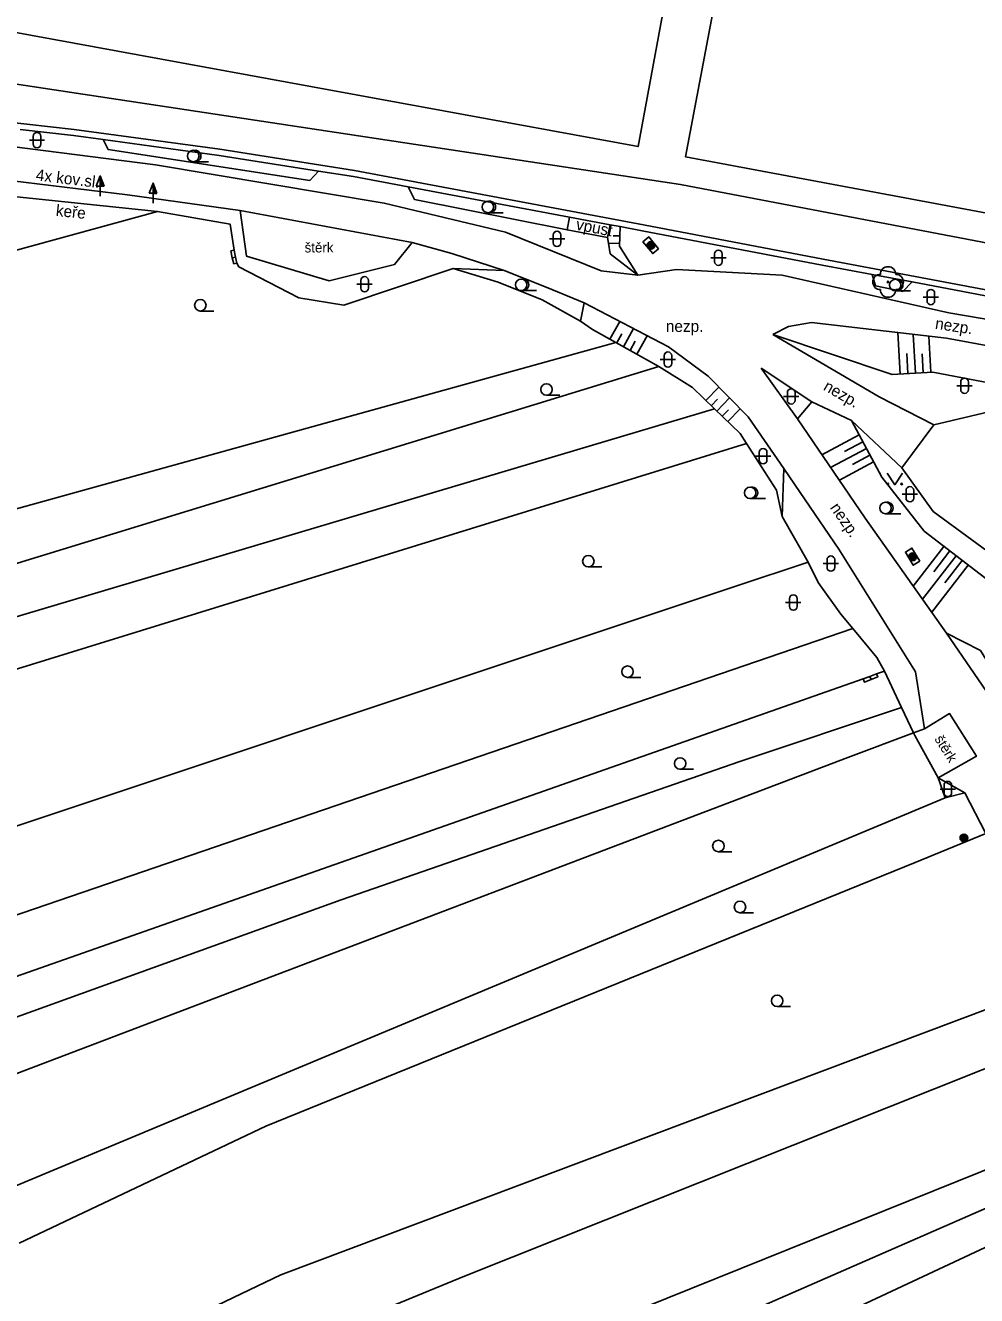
# Model space of a CAD drawing. Extents: x -595546 to -593986, y -1160845 to -1159202.
# Drawn here: x -595049.5 to -594987.4, y -1160163.2 to -1160080.3 of the extents above; entities that cross this region are included whole.
import ezdxf

# ---------------------------------------------------------------- set-up
doc = ezdxf.new("R2010")
doc.units = 0
for name, color, linetype in [('DOP - kresba z DSPS bez souradnic', 7, 'Continuous'), ('DOP - rozhrani ploch obecne', 7, 'Continuous'), ('kanalizace - povrch.  znaky - skut. velikost', 7, 'Continuous'), ('Level 22', 7, 'Continuous'), ('Level 24', 7, 'Continuous'), ('Level 25', 7, 'Continuous'), ('Level 36', 7, 'Continuous'), ('silnoproud - povrch.  znaky a  RIS  skut. velikost', 7, 'Continuous'), ('TM - dolni hrana svahu', 7, 'Continuous'), ('TM - horni hrana svahu', 7, 'Continuous'), ('TM - hranice souvisleho porostu (skupiny stromu_ kere)', 7, 'Continuous'), ('TM - letecke snimky - pomocna linie', 7, 'Continuous'), ('TM - nezpevnene cesty a chodniky', 7, 'Continuous'), ('TM - plot drateny_ kovovy - VP', 7, 'Continuous'), ('TM - podezdivka plotu - VP', 7, 'Continuous'), ('TM - popis povrchu', 7, 'Continuous'), ('TM - popis zelene', 7, 'Continuous'), ('TM - poznamka', 7, 'Continuous'), ('TM - rozhrani kultur', 7, 'Continuous'), ('TM - rozhrani ploch obecne - VP', 7, 'Continuous'), ('TM - srafovani', 7, 'Continuous'), ('TM - vjezd na pozemek', 7, 'Continuous')]:
    doc.layers.add(name, color=color, linetype=linetype)

msp = doc.modelspace()

# ---------------------------------------------------------------- linework, layer by layer
at = {"layer": 'DOP - kresba z DSPS bez souradnic'}
for points in [[(-594996.5, -1160017.71), (-595009.51, -1160088.18), (-595057.76, -1160079.35), (-595051.78, -1160044.49), (-595044.93, -1160008.53)], [(-594994.78, -1160027.28), (-595006.42, -1160088.85), (-594939.11, -1160101.43), (-594934.74, -1160078.54), (-594931.92, -1160079.05), (-594936.73, -1160104.02), (-595006.75, -1160090.67)], [(-595006.75, -1160090.67), (-595060.78, -1160082.5), (-595082.25, -1160081.41), (-595101.08, -1160081.24), (-595119.19, -1160081.99), (-595142.76, -1160083.52), (-595149.6, -1160084.27), (-595210.49, -1160092.35), (-595222.93, -1160095.19), (-595225.49, -1160095.93), (-595227.88, -1160096.99), (-595241.96, -1160105.99), (-595288.12, -1160138.81), (-595307.05, -1160111.71), (-595308.9, -1160104.34)]]:
    msp.add_lwpolyline(points, dxfattribs=at)
at = {"layer": 'DOP - rozhrani ploch obecne'}
for points in [[(-595010.97, -1160100.98), (-595064.79, -1160115.92)], [(-595053.6, -1160116.49), (-595008.16, -1160102.55)], [(-595004.53, -1160105.31), (-595063.59, -1160122.9)], [(-595002.43, -1160107.58), (-595063.52, -1160126.46)], [(-595062.49, -1160136.68), (-595003.14, -1160116.9)], [(-594995.49, -1160119.66), (-595072.53, -1160146.06)], [(-594993.94, -1160122.62), (-594993.42, -1160122.45)], [(-595060.62, -1160146.07), (-594994.81, -1160122.96)], [(-595002.86, -1160128.36), (-594992.31, -1160124.82)], [(-595052.1, -1160149.49), (-594995.81, -1160128.08)], [(-595028.9, -1160137.38), (-595002.86, -1160128.36)], [(-594994.09, -1160132.65), (-595054.14, -1160157.72)], [(-594991.43, -1160134.95), (-595033.83, -1160152.16)], [(-595060.58, -1160148.82), (-595028.9, -1160137.38)], [(-594981.93, -1160142.72), (-595032.85, -1160161.88)], [(-595020.85, -1160161.97), (-594980.93, -1160146.04)], [(-595033.83, -1160152.16), (-595049.93, -1160159.81)], [(-594979.3, -1160152), (-595029.56, -1160172.25)], [(-595027.18, -1160175.19), (-594980.21, -1160154.65)], [(-595025.32, -1160178.09), (-594977.96, -1160155.93)], [(-595032.85, -1160161.88), (-595043.2, -1160166.84)], [(-595033.86, -1160167.32), (-595020.85, -1160161.97)]]:
    msp.add_lwpolyline(points, dxfattribs=at)
at = {"layer": 'kanalizace - povrch.  znaky - skut. velikost'}
for points in [[(-595013.99, -1160092.8), (-595014.14, -1160093.62)], [(-595014.14, -1160093.62), (-595011.5, -1160094.12)], [(-595011.5, -1160094.12), (-595011.34, -1160093.29)]]:
    msp.add_lwpolyline(points, dxfattribs=at)
at = {"layer": 'Level 22'}
msp.add_circle((-594993.19, -1160097.03), 0.05, dxfattribs=at)
for centre, start, end in [((-594993.19, -1160096.53), 0, 180), ((-594993.69, -1160097.03), 90, 270), ((-594992.69, -1160097.03), 270, 90), ((-594993.19, -1160097.53), 180, 0)]:
    msp.add_arc(centre, 0.5, start, end, dxfattribs=at)
at = {"layer": 'Level 24'}
for points in [[(-595008.177, -1160094.853), (-595008.82, -1160094.088), (-595009.203, -1160094.41), (-595008.559, -1160095.175)], [(-594991.117, -1160115.27), (-594991.632, -1160114.413), (-594992.06, -1160114.67), (-594991.545, -1160115.527)]]:
    msp.add_lwpolyline(points, close=True, dxfattribs=at)
at = {"layer": 'Level 25'}
for p, q in [((-595044.892, -1160090.778), (-595044.64, -1160090.104)), ((-595044.64, -1160090.778), (-595044.892, -1160090.778)), ((-595044.64, -1160091.43), (-595044.64, -1160090.78)), ((-595041.442, -1160091.238), (-595041.19, -1160090.564)), ((-595041.19, -1160091.238), (-595041.442, -1160091.238)), ((-595041.19, -1160091.89), (-595041.19, -1160091.24))]:
    msp.add_line(p, q, dxfattribs=at)
for points in [[(-595044.39, -1160090.78), (-595044.64, -1160090.78), (-595044.64, -1160090.104), (-595044.64, -1160090.104)], [(-595044.447, -1160090.74), (-595044.6, -1160090.74), (-595044.6, -1160090.327)], [(-595044.505, -1160090.7), (-595044.56, -1160090.7), (-595044.56, -1160090.551)], [(-595040.94, -1160091.24), (-595041.19, -1160091.24), (-595041.19, -1160090.564), (-595041.19, -1160090.564)], [(-595040.997, -1160091.2), (-595041.15, -1160091.2), (-595041.15, -1160090.787)], [(-595041.055, -1160091.16), (-595041.11, -1160091.16), (-595041.11, -1160091.011)]]:
    msp.add_lwpolyline(points, close=True, dxfattribs=at)
for centre, radius in [((-595008.68, -1160094.64), 0.25), ((-595008.68, -1160094.64), 0.2), ((-595008.68, -1160094.64), 0.15), ((-595008.68, -1160094.64), 0.1), ((-595008.68, -1160094.64), 0.05), ((-594991.58, -1160114.98), 0.25), ((-594991.58, -1160114.98), 0.2), ((-594991.58, -1160114.98), 0.15), ((-594991.58, -1160114.98), 0.1), ((-594991.58, -1160114.98), 0.05), ((-594988.24, -1160133.34), 0.25), ((-594988.24, -1160133.34), 0.2), ((-594988.24, -1160133.34), 0.15), ((-594988.24, -1160133.34), 0.1), ((-594988.24, -1160133.34), 0.05)]:
    msp.add_circle(centre, radius, dxfattribs=at)
at = {"layer": 'Level 36'}
for p, q in [((-595049.266, -1160087.766), (-595048.266, -1160087.766)), ((-595049.016, -1160087.516), (-595049.016, -1160088.016)), ((-595048.516, -1160087.516), (-595048.516, -1160088.016)), ((-595038.56, -1160089.175), (-595037.56, -1160089.175)), ((-595019.32, -1160092.505), (-595018.32, -1160092.505)), ((-595015.306, -1160094.216), (-595014.306, -1160094.216)), ((-595015.056, -1160093.966), (-595015.056, -1160094.466)), ((-595014.556, -1160093.966), (-595014.556, -1160094.466)), ((-595004.766, -1160095.446), (-595003.766, -1160095.446)), ((-595004.516, -1160095.196), (-595004.516, -1160095.696)), ((-595004.016, -1160095.196), (-595004.016, -1160095.696)), ((-595027.626, -1160096.926), (-595027.626, -1160097.426)), ((-595027.126, -1160096.926), (-595027.126, -1160097.426)), ((-595027.876, -1160097.176), (-595026.876, -1160097.176)), ((-595017.15, -1160097.585), (-595016.15, -1160097.585)), ((-594992.72, -1160097.605), (-594991.72, -1160097.605)), ((-594990.646, -1160097.766), (-594990.646, -1160098.266)), ((-594990.146, -1160097.766), (-594990.146, -1160098.266)), ((-594990.896, -1160098.016), (-594989.896, -1160098.016)), ((-595038.1, -1160098.925), (-595037.225, -1160098.925)), ((-595007.816, -1160101.846), (-595007.816, -1160102.346)), ((-595007.316, -1160101.846), (-595007.316, -1160102.346)), ((-595008.066, -1160102.096), (-595007.066, -1160102.096)), ((-594988.446, -1160103.556), (-594988.446, -1160104.056)), ((-594987.946, -1160103.556), (-594987.946, -1160104.056)), ((-595015.49, -1160104.425), (-595014.615, -1160104.425)), ((-595000.016, -1160104.506), (-594999.016, -1160104.506)), ((-594999.766, -1160104.256), (-594999.766, -1160104.756)), ((-594999.266, -1160104.256), (-594999.266, -1160104.756)), ((-594988.696, -1160103.806), (-594987.696, -1160103.806)), ((-595001.846, -1160108.406), (-595000.846, -1160108.406)), ((-595001.596, -1160108.156), (-595001.596, -1160108.656)), ((-595001.096, -1160108.156), (-595001.096, -1160108.656)), ((-595002.2, -1160111.175), (-595001.2, -1160111.175)), ((-594992.266, -1160110.896), (-594991.266, -1160110.896)), ((-594992.016, -1160110.646), (-594992.016, -1160111.146)), ((-594991.516, -1160110.646), (-594991.516, -1160111.146)), ((-594993.36, -1160112.165), (-594992.36, -1160112.165)), ((-594997.176, -1160115.176), (-594997.176, -1160115.676)), ((-594996.676, -1160115.176), (-594996.676, -1160115.676)), ((-595012.76, -1160115.645), (-595011.885, -1160115.645)), ((-594997.426, -1160115.426), (-594996.426, -1160115.426)), ((-594999.626, -1160117.716), (-594999.626, -1160118.216)), ((-594999.126, -1160117.716), (-594999.126, -1160118.216)), ((-594999.876, -1160117.966), (-594998.876, -1160117.966)), ((-595010.2, -1160122.855), (-595009.325, -1160122.855)), ((-595006.77, -1160128.855), (-595005.895, -1160128.855)), ((-594989.786, -1160130.146), (-594988.786, -1160130.146)), ((-594989.536, -1160129.896), (-594989.536, -1160130.396)), ((-594989.036, -1160129.896), (-594989.036, -1160130.396)), ((-595004.27, -1160134.245), (-595003.395, -1160134.245)), ((-595002.86, -1160138.225), (-595001.985, -1160138.225)), ((-595000.43, -1160144.355), (-594999.555, -1160144.355))]:
    msp.add_line(p, q, dxfattribs=at)
msp.add_lwpolyline([(-594993.25, -1160109.52), (-594992.75, -1160110.27), (-594992.25, -1160109.52)], dxfattribs=at)
for centre, radius in [((-595038.56, -1160088.8), 0.375), ((-595019.32, -1160092.13), 0.375), ((-595017.15, -1160097.21), 0.375), ((-594992.72, -1160097.23), 0.375), ((-595038.1, -1160098.55), 0.375), ((-595015.49, -1160104.05), 0.375), ((-594993.2, -1160110.22), 0.05), ((-594992.301, -1160110.22), 0.05), ((-595002.2, -1160110.8), 0.375), ((-594993.36, -1160111.79), 0.375), ((-595012.76, -1160115.27), 0.375), ((-595010.2, -1160122.48), 0.375), ((-595006.77, -1160128.48), 0.375), ((-595004.27, -1160133.87), 0.375), ((-595002.86, -1160137.85), 0.375), ((-595000.43, -1160143.98), 0.375)]:
    msp.add_circle(centre, radius, dxfattribs=at)
for centre, radius, start, end in [((-595048.766, -1160087.516), 0.25, 0, 180), ((-595048.766, -1160088.016), 0.25, 180, 0), ((-595038.435, -1160088.8), 0.375, 260.40593, 99.59407), ((-595019.195, -1160092.13), 0.375, 260.40593, 99.59407), ((-595014.806, -1160093.966), 0.25, 0, 180), ((-595014.806, -1160094.466), 0.25, 180, 0), ((-595004.266, -1160095.196), 0.25, 0, 180), ((-595004.266, -1160095.696), 0.25, 180, 0), ((-595027.376, -1160096.926), 0.25, 0, 180), ((-595017.025, -1160097.21), 0.375, 260.40593, 99.59407), ((-594992.595, -1160097.23), 0.375, 260.40593, 99.59407), ((-595027.376, -1160097.426), 0.25, 180, 0), ((-594990.396, -1160097.766), 0.25, 0, 180), ((-594990.396, -1160098.266), 0.25, 180, 0), ((-595007.566, -1160101.846), 0.25, 0, 180), ((-595007.566, -1160102.346), 0.25, 180, 0), ((-594988.196, -1160103.556), 0.25, 0, 180), ((-594999.516, -1160104.256), 0.25, 0, 180), ((-594988.196, -1160104.056), 0.25, 180, 0), ((-594999.516, -1160104.756), 0.25, 180, 0), ((-595001.346, -1160108.156), 0.25, 0, 180), ((-595001.346, -1160108.656), 0.25, 180, 0), ((-595002.075, -1160110.8), 0.375, 260.40593, 99.59407), ((-594991.766, -1160110.646), 0.25, 0, 180), ((-594991.766, -1160111.146), 0.25, 180, 0), ((-594993.235, -1160111.79), 0.375, 260.40593, 99.59407), ((-594996.926, -1160115.176), 0.25, 0, 180), ((-594996.926, -1160115.676), 0.25, 180, 0), ((-594999.376, -1160117.716), 0.25, 0, 180), ((-594999.376, -1160118.216), 0.25, 180, 0), ((-594989.286, -1160129.896), 0.25, 0, 180), ((-594989.286, -1160130.396), 0.25, 180, 0)]:
    msp.add_arc(centre, radius, start, end, dxfattribs=at)
at = {"layer": 'silnoproud - povrch.  znaky a  RIS  skut. velikost'}
for points in [[(-595036.11, -1160095), (-595035.9, -1160094.95)], [(-595036.02, -1160095.46), (-595036.11, -1160095)], [(-595035.8, -1160095.41), (-595036.02, -1160095.46)], [(-595035.9, -1160094.95), (-595035.85, -1160095.18)], [(-595035.85, -1160095.18), (-595035.8, -1160095.41)], [(-595035.75, -1160095.6), (-595035.8, -1160095.41)], [(-595036.02, -1160095.46), (-595035.92, -1160095.84)], [(-595035.92, -1160095.84), (-595035.71, -1160095.8)], [(-595035.71, -1160095.8), (-595035.75, -1160095.6)], [(-594994.37, -1160122.79), (-594994.81, -1160122.96)], [(-594993.94, -1160122.62), (-594994.37, -1160122.79)], [(-594994.29, -1160123), (-594994.37, -1160122.79)], [(-594993.94, -1160122.62), (-594993.86, -1160122.83), (-594994.29, -1160123)], [(-594994.29, -1160123), (-594994.73, -1160123.17), (-594994.81, -1160122.96)]]:
    msp.add_lwpolyline(points, dxfattribs=at)
at = {"layer": 'TM - dolni hrana svahu'}
msp.add_lwpolyline([(-595009.54, -1160096.58), (-595011.34, -1160095.19), (-595011.44, -1160094.49), (-595011.5, -1160094.12)], dxfattribs=at)
at = {"layer": 'TM - horni hrana svahu'}
for points in [[(-595009.54, -1160096.58), (-595010.73, -1160094.69), (-595010.69, -1160093.41)], [(-594990.26, -1160102.92), (-594992.92, -1160103.07), (-595000.71, -1160100.47)], [(-594983.3, -1160104.25), (-594990.26, -1160102.92)], [(-595000.11, -1160112.34), (-594999.99, -1160109.22)]]:
    msp.add_lwpolyline(points, dxfattribs=at)
at = {"layer": 'TM - hranice souvisleho porostu (skupiny stromu_ kere)'}
for points in [[(-595030.39, -1160089.78), (-595030.96, -1160090.4), (-595044.12, -1160088.37), (-595044.45, -1160087.72)], [(-595014.14, -1160093.62), (-595024.11, -1160091.65), (-595024.52, -1160090.81)], [(-595021.6, -1160096.14), (-595018.26, -1160096.27)], [(-594991.62, -1160097.03), (-594992.22, -1160097.64), (-594994.01, -1160097.29), (-594994.23, -1160096.54)], [(-595013.28, -1160099.58), (-595013.04, -1160098.38)], [(-594998.17, -1160104.86), (-594999.11, -1160105.97)], [(-594995.58, -1160106.08), (-594993.59, -1160109.78)], [(-594993.59, -1160109.78), (-594990.84, -1160113.3)], [(-594990.84, -1160113.3), (-594985.96, -1160117.05)], [(-594989.37, -1160119.96), (-594987.16, -1160121.1), (-594984.77, -1160124.95)]]:
    msp.add_lwpolyline(points, dxfattribs=at)
at = {"layer": 'TM - letecke snimky - pomocna linie'}
msp.add_lwpolyline([(-594989.21, -1160099.04), (-594938.3, -1160107.72), (-594934.32, -1160107.81)], dxfattribs=at)
at = {"layer": 'TM - nezpevnene cesty a chodniky'}
for points in [[(-595067.13, -1160086.12), (-595059.73, -1160087.2), (-595050.42, -1160088.17), (-595041.02, -1160089.38), (-595026.09, -1160091.88), (-595018.18, -1160093.78), (-595011.92, -1160096.3)], [(-595042.86, -1160091.34), (-595055.39, -1160089.82)], [(-595035.5, -1160092.35), (-595042.86, -1160091.34)], [(-595035.5, -1160092.35), (-595024.26, -1160094.44)], [(-595024.26, -1160094.44), (-595021.67, -1160095.16), (-595018.26, -1160096.27)], [(-595018.26, -1160096.27), (-595015.52, -1160097.37), (-595013.04, -1160098.38)], [(-595009.54, -1160096.58), (-595007.01, -1160096.22), (-595000.1, -1160096.59), (-594989.21, -1160099.04)], [(-595011.92, -1160096.3), (-595009.54, -1160096.58)], [(-595013.04, -1160098.38), (-595007.52, -1160101.27)], [(-595000.71, -1160100.47), (-594999.7, -1160099.94), (-594998.18, -1160099.68)], [(-594989.38, -1160100.7), (-594998.18, -1160099.68)], [(-594990.19, -1160106.37), (-594993.77, -1160104.53), (-595000.71, -1160100.47)], [(-594946.29, -1160108.3), (-594958.32, -1160106.38), (-594982.18, -1160102.02), (-594989.38, -1160100.7)], [(-595004.94, -1160103.19), (-595007.52, -1160101.27)], [(-595001.47, -1160102.66), (-594999.11, -1160105.97)], [(-594998.17, -1160104.86), (-595001.47, -1160102.66)], [(-595004.94, -1160103.19), (-595002.33, -1160105.84), (-594999.99, -1160109.22)], [(-594995.58, -1160106.08), (-594998.17, -1160104.86)], [(-594989.37, -1160119.96), (-594994.68, -1160112.46), (-594999.11, -1160105.97)], [(-594992.3, -1160109.17), (-594995.58, -1160106.08)], [(-594999.99, -1160109.22), (-594998.6, -1160111.25), (-594996.41, -1160114.48)], [(-594996.41, -1160114.48), (-594991.4, -1160122.5), (-594990.81, -1160126.21)], [(-594989.37, -1160119.96), (-594986.53, -1160124.12), (-594985.44, -1160124.55), (-594984.77, -1160124.95)], [(-594990.81, -1160126.21), (-594989.17, -1160125.22), (-594987.42, -1160128.01), (-594989.92, -1160129.42)], [(-594988.17, -1160130.4), (-594989.92, -1160129.42)]]:
    msp.add_lwpolyline(points, dxfattribs=at)
at = {"layer": 'TM - plot drateny_ kovovy - VP'}
for points in [[(-595066.45, -1160084.81), (-595046.33, -1160087.06), (-595036.82, -1160088.36), (-595028.03, -1160089.75)], [(-595028.03, -1160089.75), (-595009.17, -1160093.3), (-594997.43, -1160095.53), (-594981.61, -1160098.52)], [(-595062.53, -1160092.25), (-595055.11, -1160090.95), (-595040.89, -1160092.43)], [(-595040.89, -1160092.43), (-595067.9, -1160099.83)], [(-595040.89, -1160092.43), (-595036.16, -1160093.25), (-595035.9, -1160094.95)], [(-595035.58, -1160096.03), (-595035.71, -1160095.8)], [(-595031.66, -1160098.06), (-595028.72, -1160098.54), (-595021.6, -1160096.14)], [(-595021.6, -1160096.14), (-595018.66, -1160097.04), (-595015.78, -1160098.2), (-595013.28, -1160099.58)], [(-595010.97, -1160100.98), (-595012.48, -1160100.13)], [(-595008.16, -1160102.55), (-595010.97, -1160100.98)], [(-595004.53, -1160105.31), (-595005.96, -1160103.93)], [(-595002.85, -1160106.93), (-595004.53, -1160105.31)], [(-594986.61, -1160105.51), (-594990.19, -1160106.37)], [(-595002.85, -1160106.93), (-595002.43, -1160107.58)], [(-595002.43, -1160107.58), (-595000.47, -1160110.62), (-595000.11, -1160112.34)], [(-594992.3, -1160109.17), (-594990.25, -1160112.01)], [(-594990.25, -1160112.01), (-594984.87, -1160115.96)], [(-594998.4, -1160115.32), (-595003.14, -1160116.9)], [(-594997.76, -1160116.66), (-594998.4, -1160115.32)], [(-594995.49, -1160119.66), (-594996.27, -1160118.73)], [(-594993.92, -1160121.55), (-594995.49, -1160119.66)], [(-594995.81, -1160128.08), (-594991.53, -1160126.47)], [(-594990.81, -1160126.21), (-594991.53, -1160126.47)], [(-594991.53, -1160126.47), (-594991.45, -1160126.65)], [(-594989.47, -1160130.73), (-594989.92, -1160129.42)], [(-594989.47, -1160130.73), (-594994.09, -1160132.65)], [(-594988.17, -1160130.4), (-594989.47, -1160130.73)], [(-594991.43, -1160134.95), (-594986.8, -1160133.06)]]:
    msp.add_lwpolyline(points, dxfattribs=at)
at = {"layer": 'TM - podezdivka plotu - VP'}
for points in [[(-595046.38, -1160087.46), (-595049.87, -1160087.07)], [(-595046.38, -1160087.46), (-595044.45, -1160087.72)], [(-595044.45, -1160087.72), (-595036.88, -1160088.76)], [(-595036.88, -1160088.76), (-595030.39, -1160089.78)], [(-595030.39, -1160089.78), (-595028.1, -1160090.14), (-595024.52, -1160090.81)], [(-595024.52, -1160090.81), (-595013.99, -1160092.8)], [(-595011.34, -1160093.29), (-595013.99, -1160092.8)], [(-595010.69, -1160093.41), (-595011.34, -1160093.29)], [(-594994.23, -1160096.54), (-594997.5, -1160095.92), (-595009.24, -1160093.69), (-595010.69, -1160093.41)], [(-594991.62, -1160097.03), (-594994.23, -1160096.54)], [(-594981.68, -1160098.91), (-594991.62, -1160097.03)]]:
    msp.add_lwpolyline(points, dxfattribs=at)
at = {"layer": 'TM - rozhrani kultur'}
for points in [[(-594993.42, -1160122.45), (-594992.31, -1160124.82)], [(-594992.31, -1160124.82), (-594991.53, -1160126.47)]]:
    msp.add_lwpolyline(points, dxfattribs=at)
at = {"layer": 'TM - rozhrani ploch obecne - VP'}
msp.add_lwpolyline([(-595024.26, -1160094.44), (-595025.42, -1160095.88), (-595029.68, -1160096.95), (-595035.08, -1160095.35), (-595035.5, -1160092.35)], dxfattribs=at)
at = {"layer": 'TM - srafovani'}
for points in [[(-595010.72, -1160094.52), (-595011.44, -1160094.49)], [(-595010.71, -1160094.02), (-595011.14, -1160094.01)], [(-595011.35, -1160100.77), (-595010.7, -1160099.61)], [(-595010.91, -1160101.01), (-595010.58, -1160100.42)], [(-595010.47, -1160101.26), (-595009.81, -1160100.07)], [(-594992.4, -1160103.04), (-594992.55, -1160100.33)], [(-595010.04, -1160101.5), (-595009.7, -1160100.9)], [(-595009.6, -1160101.74), (-595008.92, -1160100.54)], [(-594991.4, -1160102.98), (-594991.54, -1160100.45)], [(-594990.4, -1160102.93), (-594990.53, -1160100.57)], [(-594991.9, -1160103.01), (-594991.97, -1160101.7)], [(-594990.9, -1160102.96), (-594990.97, -1160101.73)], [(-595005.1, -1160104.76), (-595004.25, -1160103.89)], [(-595004.74, -1160105.11), (-595004.32, -1160104.68)], [(-595004.38, -1160105.46), (-595003.55, -1160104.6)], [(-595004.02, -1160105.8), (-595003.61, -1160105.38)], [(-595003.66, -1160106.15), (-595002.85, -1160105.31)], [(-594995.08, -1160107.01), (-594997.51, -1160108.32)], [(-594994.84, -1160107.46), (-594996.03, -1160108.1)], [(-594994.6, -1160107.9), (-594996.94, -1160109.15)], [(-594994.37, -1160108.34), (-594995.51, -1160108.95)], [(-594994.13, -1160108.78), (-594996.37, -1160109.98)], [(-594989.54, -1160114.3), (-594991.54, -1160116.9)], [(-594988.75, -1160114.91), (-594990.94, -1160117.75)], [(-594989.15, -1160114.6), (-594990.19, -1160115.96)], [(-594988.35, -1160115.21), (-594989.49, -1160116.69)], [(-594987.96, -1160115.52), (-594990.33, -1160118.6)]]:
    msp.add_lwpolyline(points, dxfattribs=at)
at = {"layer": 'TM - vjezd na pozemek'}
for points in [[(-595035.58, -1160096.03), (-595031.66, -1160098.06)], [(-595013.28, -1160099.58), (-595012.48, -1160100.13)], [(-595005.96, -1160103.93), (-595008.16, -1160102.55)], [(-594990.19, -1160106.37), (-594992.3, -1160109.17)], [(-594998.4, -1160115.32), (-595000.11, -1160112.34)], [(-594996.27, -1160118.73), (-594997.76, -1160116.66)], [(-594993.42, -1160122.45), (-594993.92, -1160121.55)], [(-594989.92, -1160129.42), (-594991.45, -1160126.65)], [(-594986.8, -1160133.06), (-594988.17, -1160130.4)]]:
    msp.add_lwpolyline(points, dxfattribs=at)

# ---------------------------------------------------------------- texts
at = {"layer": 'TM - popis povrchu'}
for s, height, p in [('štěrk', 0.65, (-595031.29, -1160095.1)), ('nezp.', 0.75, (-595007.7, -1160100.29))]:
    msp.add_text(s, height=height, dxfattribs=at).set_placement(p)
for s, height, rotation, p in [('nezp.', 0.75, 351.32013, (-594990.15, -1160100.08)), ('nezp.', 0.75, 330.00203, (-594997.47, -1160104.05)), ('nezp.', 0.75, 304.73762, (-594997.01, -1160111.77)), ('štěrk', 0.65, 302, (-594990.18, -1160126.88))]:
    msp.add_text(s, height=height, rotation=rotation, dxfattribs=at).set_placement(p)
at = {"layer": 'TM - popis zelene'}
msp.add_text('keře', height=0.75, rotation=354.05812, dxfattribs=at).set_placement((-595047.56, -1160092.71))
at = {"layer": 'TM - poznamka'}
for s, rotation, p in [('4x kov.sl.', 353.08331, (-595048.87, -1160090.39)), ('vpust', 349.27555, (-595013.61, -1160093.61))]:
    msp.add_text(s, height=0.75, rotation=rotation, dxfattribs=at).set_placement(p)

doc.saveas('drawing.dxf')
